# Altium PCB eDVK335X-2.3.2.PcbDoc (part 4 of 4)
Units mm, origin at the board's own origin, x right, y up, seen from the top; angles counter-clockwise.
Board outline 100.04 x 80.07 mm, 4 copper layers (Top Layer, Layer 1, Layer 2, Bottom Layer), stack 0.569 mm thick; 245 components, 272 nets, 1313 pads, 662 vias.
Unrouted connection lines stored in the file: 1.
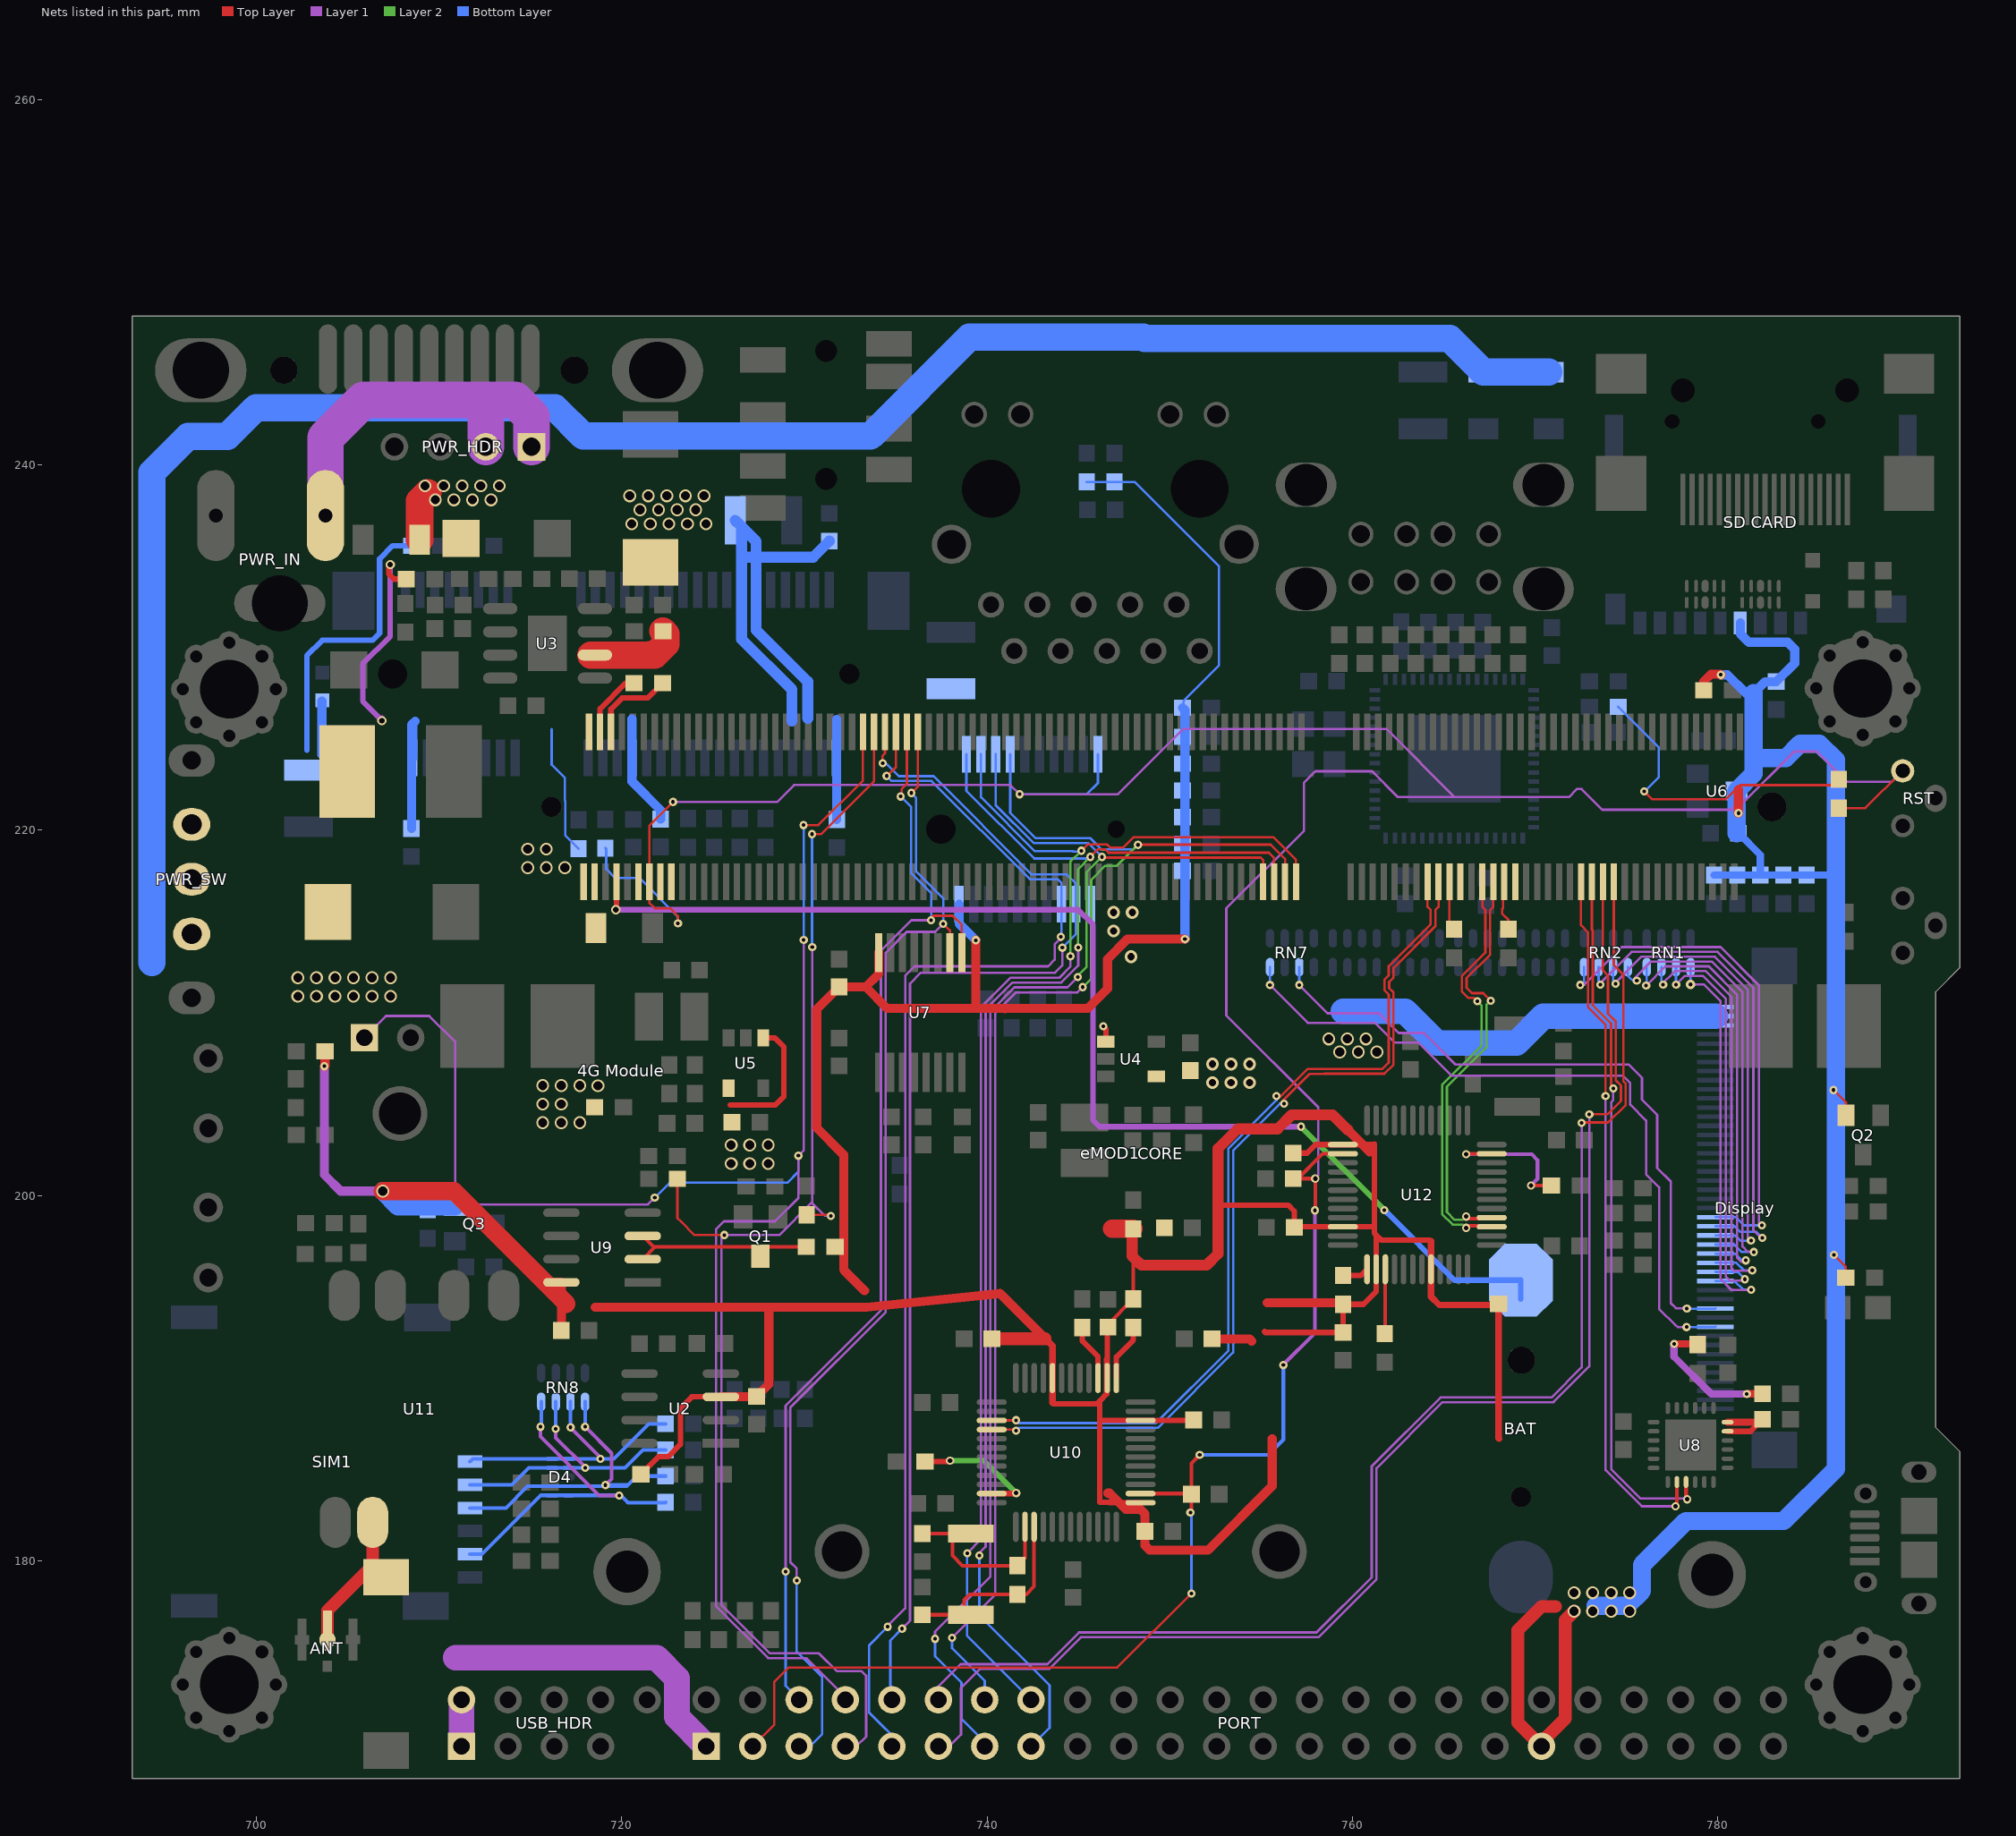
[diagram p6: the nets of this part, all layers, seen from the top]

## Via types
v1: diameter 0.45, hole 0.2, Top Layer to Bottom Layer, tented both sides, 424 vias
v2: diameter 0.7, hole 0.5, Top Layer to Bottom Layer, tented both sides, 146 vias
v3: diameter 0.45, hole 0.25, Top Layer to Bottom Layer, tented both sides, 55 vias
v4: diameter 0.5, hole 0.3, Top Layer to Bottom Layer, tented both sides, 17 vias
v5: diameter 0.7, hole 0.4, Top Layer to Bottom Layer, tented both sides, 13 vias
v6: diameter 0.66, hole 0.33, Top Layer to Bottom Layer, tented both sides, 4 vias
v7: diameter 0.75, hole 0.5, Top Layer to Bottom Layer, tented both sides, 1 vias
v8: diameter 0.5, hole 0.2, Top Layer to Bottom Layer, tented both sides, 1 vias
v9: diameter 0.45, hole 0.3, Top Layer to Bottom Layer, tented both sides, 1 vias

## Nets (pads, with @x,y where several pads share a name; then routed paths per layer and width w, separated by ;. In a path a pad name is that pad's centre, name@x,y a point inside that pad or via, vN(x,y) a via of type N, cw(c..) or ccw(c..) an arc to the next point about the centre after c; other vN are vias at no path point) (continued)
NetR104_2: R104.2 U10.37 | length 3.1
  Top Layer w0.3: U10.37@747.076,190.012 747.076,191.163 748.009,192.096 R104.2@748.009,192.77
NetR107_1: R107.1 U10.11 | length 7.1
  Top Layer w0.3: R107.1@736.604,185.429 737.912,185.429 v3(737.976,185.492) ; U10.11@740.251,183.687 741.568,183.687 v3(741.595,183.714)
  Layer 2 w0.3: v3(737.976,185.492) 739.817,185.492 v3(741.595,183.714)
NetR130_1: R130.1 U12.39 | length 3.5
  Top Layer w0.2: R130.1@761.774,192.446 761.802,192.474 761.802,193.49 U12.39@761.802,195.965
NetR131_2: R131.2 U12.37 | length 1.5
  Top Layer w0.3: R131.2@759.488,195.621 760.457,195.621 U12.37@760.802,195.965
NetR133_1: R133.1 U12.11 | length 8.1
  Top Layer w0.2: v3(766.219,202.263) 766.246,202.29 U12.11@767.627,202.29 ; v3(769.775,200.548) R133.1@770.892,200.548
  Layer 1 w0.2: v3(766.219,202.263) 769.817,202.263 770.13,201.95 770.13,200.904 v3(769.775,200.548)
NetR135_1: R135.1 U10.39 | length 3.1
  Top Layer w0.3: R135.1@745.215,192.77 745.215,192.033 746.076,191.172 U10.39@746.076,190.012
PWRON: CORE.190
R0: Display.22 RN2.8 | length 28.3
  Layer 1 w0.13: v1@772.673,211.53 774.743,213.6 780.16,213.6 782.25,211.51 782.25,198.42 782.3,198.37 v1(782.418,198.37)
  Bottom Layer w0.13: v1@772.676,211.533 RN2.8@772.676,212.509 ; Display.22@779.871,198.819 780.991,198.819 781.44,198.37 v1(782.418,198.37)
  other v1: 772.473,211.53
R1: Display.21 RN2.7 | length 27.8
  Layer 1 w0.13: v1@773.673,211.53 773.673,211.73 775.283,213.34 779.996,213.34 781.95,211.386 781.95,198.1 782.34,197.71 v1@782.34,197.68 ; v1@782.34,197.68 v1(782.438,197.68)
  Bottom Layer w0.13: RN2.7@773.476,212.509 773.476,211.727 v1@773.673,211.53 ; Display.21@779.871,198.319 780.921,198.319 781.22,198.02 782.098,198.02 v1(782.438,197.68)
  other v1: 773.573,211.54
R2: Display.20 RN2.6 | length 25.8
  Layer 1 w0.13: v1@774.473,211.53 774.473,211.73 775.813,213.07 779.841,213.07 781.65,211.261 781.65,197.51 781.71,197.45 781.71,197.421 v1(781.818,197.53)
  Bottom Layer w0.13: RN2.6@774.276,212.509 774.276,211.767 v1@774.493,211.55 ; Display.20@779.871,197.819 780.941,197.819 781.23,197.53 v1(781.818,197.53)
  other v1: 774.413,211.6
R3: Display.19 RN2.5 | length 25.2
  Layer 1 w0.13: v1@775.48,211.64 775.48,211.937 776.353,212.81 779.677,212.81 781.35,211.137 781.35,197.21 781.63,196.93 781.85,196.93 v1@781.92,196.86 ; v1@781.92,196.861 v1(781.968,196.91)
  Bottom Layer w0.13: RN2.5@775.076,212.509 775.076,212.044 v1@775.48,211.64 ; Display.19@779.871,197.319 780.901,197.319 781.31,196.91 v1(781.968,196.91)
  other v1: 775.57,211.77
R4: Display.18 RN1.8 | length 23.9
  Layer 1 w0.13: v1@776.11,211.53 777.13,212.55 779.513,212.55 781.05,211.013 781.05,196.6 781.28,196.37 v1@781.53,196.37 ; v1@781.53,196.3 v1@781.53,196.37 ; v1(781.538,196.45) 781.53,196.441 v1@781.53,196.37
  Bottom Layer w0.13: v1@776.11,211.53 776.113,211.533 RN1.8@776.113,212.509 ; Display.18@779.871,196.819 780.938,196.819 781.307,196.45 v1(781.538,196.45)
  other v1: 776.08,211.49
R5: Display.17 RN1.7 | length 24
  Layer 1 w0.13: v1@776.91,211.54 777.66,212.29 779.349,212.29 780.75,210.889 780.75,196.03 780.9,195.88 781.679,195.88 781.729,195.83 781.81,195.83 v1@781.888,195.908
  Bottom Layer w0.13: v1@776.91,211.54 776.913,211.543 RN1.7@776.913,212.509 ; Display.17@779.871,196.319 781.014,196.319 781.423,195.91 v1(781.888,195.91)
  other v1: 777.01,211.54
R6: Display.16 RN1.6 | length 22.6
  Layer 1 w0.13: v1(777.72,211.55) 778.2,212.03 779.184,212.03 780.45,210.764 780.45,195.544 780.644,195.35 781.41,195.35 781.43,195.37 781.44,195.37 v1@781.488,195.418
  Bottom Layer w0.13: RN1.6@777.713,212.509 777.713,211.557 v1(777.72,211.55) ; Display.16@779.871,195.819 781.089,195.819 v1(781.488,195.42)
R7: Display.15 RN1.5 | length 22.3
  Layer 1 w0.13: v8(778.51,211.56) 779.23,211.56 780.15,210.64 780.15,195.42 780.74,194.83 781.81,194.83 v1(781.83,194.85)
  Bottom Layer w0.13: v8@778.513,211.563 RN1.5@778.513,212.509 ; Display.15@779.871,195.319 780.931,195.319 781.4,194.85 v1(781.83,194.85)
  Bottom Layer w0.2: v8(778.51,211.56) v8@778.513,211.563
RESETOUTn: C70.1 C89.1 CORE.192 eMOD1.2 PORT.3 R8.1 R49.2 RST.1 U10.26 U12.26 | length 198.4
  Top Layer w0.13: v1(722.81,221.55) 721.511,220.251 CORE.192@721.511,217.18 721.511,216.035 721.816,215.729 722.651,215.729 723.08,215.3 v1(723.08,214.9) ; PORT.3@727.17,169.85 728.34,171.02 728.34,173.36 729.14,174.16 747.13,174.16 v1(751.184,178.214) ; R8.1@786.63,221.213 788.083,221.213 RST.1@790.12,223.25
  Top Layer w0.2: U10.26@748.4,183.687 751.147,183.687 C70.1@751.184,183.651 ; v1(751.13,182.65) 751.184,182.704 C70.1@751.184,183.651 ; v1(751.64,185.8) 751.184,185.344 C70.1@751.184,183.651 ; C89.1@756.757,200.929 C89.1@757.011,200.929 ; C89.1@756.884,200.802 C89.1@757.011,200.929 ; v1(757.94,199.19) 757.964,199.214 v3(757.964,200.929) C89.1@757.011,200.929 ; U12.26@759.477,202.29 758.372,202.29 C89.1@757.011,200.929
  Layer 1 w0.13: v1(722.81,221.55) 728.51,221.55 729.44,222.48 741.27,222.48 v1(741.78,221.97) 747.16,221.97 750.73,225.54 761.88,225.54 765.6,221.82 ; v3(757.964,200.929) 758.13,201.096 758.13,204.83 753.1,209.86 753.1,215.73 757.35,219.98 757.35,222.61 757.97,223.23 761.08,223.23 762.49,221.82 765.6,221.82 ; 784.88,224.31 784.19,224.31 ; RST.1@790.12,223.25 789.52,222.65 787.08,222.65 785.42,224.31 784.19,224.31 ; 765.6,221.82 771.85,221.82 772.285,222.255 772.545,222.255 773.68,221.12 780.718,221.12 780.958,221.36 781.24,221.36 784.19,224.31
  Layer 1 w0.2: v1(756.22,190.72) 756.22,190.75 757.94,192.47 v1(757.94,199.19)
  Bottom Layer w0.13: R49.2@719.1,219.023 719.15,218.973 719.15,217.88 719.65,217.38 720.98,217.38 723.08,215.28 v1(723.08,214.9) ; v1(741.78,221.97) 745.46,221.97 746.07,222.58 eMOD1.2@746.07,224.16 ; v1(751.13,182.65) 751.184,182.596 v1(751.184,178.214)
  Bottom Layer w0.2: v1(751.64,185.8) 755.39,185.8 756.22,186.63 v1(756.22,190.72)
SPI1_CS0_/_UART5_TXD: CORE.80 eMOD1.16 PORT.13 | length 75.2
  Top Layer w0.13: v1(746.289,218.54) 746.29,218.538 746.29,218.5 754.98,218.5 755.111,218.369 CORE.80@755.111,217.18
  Layer 1 w0.13: v1(737.15,175.73) 737.15,176.12 740.18,179.15 740.18,210.087 741.493,211.4 744.399,211.4 v1(744.969,211.97)
  Layer 2 w0.13: v1(744.969,211.97) 744.94,211.998 744.94,212 744.97,212.03 744.97,212.04 745.44,212.51 745.44,217.691 v1(746.289,218.54)
  Bottom Layer w0.13: v1(737.15,175.73) 737.15,174.78 737.18,174.75 738.6,173.33 738.6,171.35 739.87,170.08 PORT.13@739.87,169.85 ; eMOD1.16@740.47,224.16 740.47,221.38 742.55,219.3 745.528,219.3 v1(746.289,218.54)
SPI1_D0_/_UART5_CTSN: CORE.78 eMOD1.20 PORT.15 | length 77
  Top Layer w0.13: v1(745.659,218.54) 746.079,218.96 746.462,218.96 746.652,218.77 755.43,218.77 755.711,218.489 CORE.78@755.711,217.18
  Layer 1 w0.13: v1(739.58,180.3) 739.57,180.31 739.57,180.43 739.92,180.78 739.92,210.195 741.385,211.66 744.058,211.66 744.989,212.591 v1(744.989,213.58)
  Layer 2 w0.13: v1(744.989,213.58) 744.97,213.58 744.97,217.851 v1(745.659,218.54)
  Bottom Layer w0.13: eMOD1.20@738.87,224.16 738.87,222.16 742.58,218.45 745.659,218.45 v1(745.659,218.54) ; v1(739.58,180.3) 739.58,177.02 743.42,173.18 743.42,170.86 PORT.15@742.41,169.85
SPI1_D1_/_UART5_RTSN: CORE.74 eMOD1.18 PORT.16 | length 75.1
  Top Layer w0.13: v1(745.169,218.88) 745.509,219.22 746.57,219.22 746.735,219.055 747.457,219.055 748.022,219.62 755.68,219.62 756.911,218.389 CORE.74@756.911,217.18
  Layer 1 w0.13: v1(738.91,180.42) 739.66,181.17 739.66,210.302 741.278,211.92 743.95,211.92 744.56,212.53 v1(744.56,213.1)
  Layer 2 w0.13: v1(744.56,213.1) 744.56,218.271 v1(745.169,218.88)
  Bottom Layer w0.13: v1(738.91,180.42) 738.91,175.89 PORT.16@742.41,172.39 ; eMOD1.18@739.67,224.16 739.67,221.8 742.62,218.85 744.7,218.85 744.71,218.84 745.18,218.84 745.18,218.868 v1(745.169,218.88)
SPI1_SCLK_/_UART5_RXD: CORE.76 eMOD1.14 PORT.14 | length 75.1
  Top Layer w0.13: v1(748.259,219.2) 748.259,219.041 748.26,219.04 748.43,219.21 755.53,219.21 756.311,218.429 CORE.76@756.311,217.18
  Layer 1 w0.13: v1(738.08,175.78) 740.44,178.14 740.44,209.979 741.581,211.12 744.95,211.12 v1(745.24,211.41)
  Layer 2 w0.13: v1(745.24,211.41) 745.7,211.87 745.7,217.28 746.47,218.05 747.109,218.05 v1(748.259,219.2)
  Bottom Layer w0.13: v1(738.08,175.78) 738.08,175.22 739.87,173.43 PORT.14@739.87,172.39 ; eMOD1.14@741.27,224.16 741.27,220.95 742.65,219.57 745.64,219.57 746.25,218.96 748.019,218.96 v1(748.259,219.2)
TXEN: Q1.C R98.2 U9.2 U9.3 | length 10.2
  Top Layer w0.2: U9.2@721.149,196.519 721.822,197.192 ; U9.3@721.149,197.789 721.746,197.192 721.822,197.192 ; R98.2@730.105,197.192 721.822,197.192
UART0_RXD: CORE.28 U8.21 | length 38.7
  Top Layer w0.13: CORE.28@773.111,217.18 773.111,214.566 773.153,214.525 773.153,210.425 774.158,209.42 774.158,205.792 774.211,205.792 v1(774.278,205.86)
  Top Layer w0.2: U8.21@778.262,184.319 778.262,183.438 v3(778.329,183.371)
  Layer 1 w0.13: v1(774.278,205.86) 774.278,205.218 774.17,205.11 774.17,185.028 775.788,183.41 778.29,183.41 v3(778.329,183.371)
UART0_TXD: CORE.30 U8.20 | length 38.8
  Top Layer w0.13: CORE.30@772.511,217.18 772.511,214.799 772.893,214.417 772.893,210.317 773.85,209.36 773.85,205.47 773.84,205.46 773.848,205.46 v1(773.858,205.45)
  Top Layer w0.2: v3(777.694,182.99) 777.762,183.059 U8.20@777.762,184.319
  Layer 1 w0.13: v1(773.858,205.45) 773.858,184.972 775.84,182.99 v3(777.694,182.99)
UART1_RXD: CORE.145 PORT.6 U7.9 | length 62.3
  Top Layer w0.13: v1(735.269,221.85) 735.33,221.85 735.33,222.27 735.611,222.551 CORE.145@735.611,225.38 ; v1(736.94,215.07) 736.94,215.23 737.03,215.32 738.12,215.32 738.615,214.825 U7.9@738.615,213.299
  Layer 1 w0.13: v1(728.97,179.41) 728.97,188.5 734.19,193.72 734.19,213.4 735.86,215.07 v1(736.94,215.07)
  Bottom Layer w0.13: v1(728.97,179.41) 728.97,173.16 729.74,172.39 PORT.6@730.31,172.39 ; v1(735.269,221.85) 735.85,221.268 735.85,217.65 736.94,216.56 v1(736.94,215.07)
UART1_TXD: CORE.143 PORT.5 U7.10 | length 63.5
  Top Layer w0.13: v1(735.85,222.04) 736.211,222.401 CORE.143@736.211,225.38 ; v1(737.6,214.88) 737.965,214.515 U7.10@737.965,213.299
  Layer 1 w0.13: v1(729.58,178.92) 729.58,179.58 729.23,179.93 729.23,188.392 734.45,193.612 734.45,213.292 735.598,214.44 737.16,214.44 v1(737.6,214.88)
  Bottom Layer w0.13: v1(729.58,178.92) 729.58,175.03 730.97,173.64 730.97,170.51 PORT.5@730.31,169.85 ; v1(735.85,222.04) 736.11,221.78 736.11,217.77 737.6,216.28 v1(737.6,214.88)
UART2_RXD: CORE.153 P1.1 PORT.8 | length 98.3
  Top Layer w0.13: v1(729.95,220.28) 730.77,220.28 733.19,222.7 733.19,225.359 CORE.153@733.211,225.38
  Layer 1 w0.13: P1.1@705.91,208.65 707.09,209.83 709.46,209.83 710.89,208.4 710.89,200.27 711.65,199.51 721.43,199.51 v1(721.81,199.89) ; v1(729.96,214) 729.96,214.04 729.97,214.03 729.97,202.48 v1(729.67,202.18) 729.67,199.87 728.39,198.59 725.6,198.59 725.16,198.15 725.16,177.53 728.01,174.68 730.1,174.68 732.39,172.39 PORT.8@732.85,172.39
  Bottom Layer w0.13: v1(721.81,199.89) 722.62,200.7 729.07,200.7 729.67,201.3 729.67,202.01 729.82,202.16 729.69,202.16 v1(729.67,202.18) ; v1(729.96,214) v1@729.96,220.27
  Bottom Layer w0.2: v1(729.95,220.28) v1@729.96,220.27
UART2_TXD: CORE.151 PORT.7 R19.2 R100.1 | length 74.7
  Top Layer w0.13: R19.2@723.047,200.91 723.047,198.773 723.23,198.59 723.98,197.84 v1(725.62,197.84) ; R100.1@730.131,198.945 731.385,198.945 v1(731.44,198.89) ; v1(730.419,219.79) 730.41,219.79 730.45,219.79 730.46,219.78 730.91,219.78 733.811,222.681 CORE.151@733.811,225.38
  Layer 1 w0.13: v1(730.429,213.61) 730.429,199.581 ; v1(731.44,198.89) 731.12,198.89 730.429,199.581 ; PORT.7@732.85,169.85 733.38,170.38 733.38,173.71 733.13,173.96 731.778,173.96 730.798,174.94 728.118,174.94 725.45,177.608 725.45,197.67 v1(725.62,197.84) 728.636,197.84 730.403,199.607 730.429,199.581
  Bottom Layer w0.13: v1(730.419,219.79) 730.419,213.619 730.41,213.61 v1(730.429,213.61)
UART3_RXD: CORE.149 eMOD1.3 PORT.10 | length 68.6
  Top Layer w0.13: v1(734.28,223.67) 734.28,224.08 734.411,224.211 CORE.149@734.411,225.38
  Layer 1 w0.13: v1(735.35,176.29) 735.78,176.72 735.78,211.6 736.38,212.2 741.19,212.2 743.72,212.2 744.12,212.6 v1(744.12,213.57)
  Bottom Layer w0.13: v1(734.28,223.67) 734.46,223.67 735.17,222.96 737.07,222.96 742.45,217.58 744.36,217.58 744.87,217.07 eMOD1.3@744.87,215.96 744.87,214.31 744.13,213.57 v1(744.12,213.57) ; v1(735.35,176.29) 734.7,175.64 734.7,173.08 PORT.10@735.39,172.39
UART3_TXD: CORE.147 eMOD1.5 PORT.9 | length 71.4
  Top Layer w0.13: v1(734.5,222.97) 734.51,222.98 734.53,222.98 735.011,223.461 CORE.147@735.011,225.38
  Layer 1 w0.13: v1(734.56,176.39) 734.56,176.44 735.52,177.4 735.52,212.04 736.03,212.55 743.34,212.55 743.7,212.91 743.7,213.744 743.946,213.99 744.04,213.99 v1(744.04,214.16)
  Bottom Layer w0.13: v1(734.5,222.97) 734.77,222.7 736.963,222.7 742.342,217.32 743.87,217.32 744.07,217.12 eMOD1.5@744.07,215.96 744.07,214.19 v1(744.04,214.16) ; v1(734.56,176.39) 733.54,175.37 733.54,171.7 PORT.9@735.39,169.85
UART4_RXD: CORE.24 PORT.12 | length 75.7
  Top Layer w0.13: v1(772.548,203.98) 772.57,203.98 772.59,204 773.99,204 774.958,204.968 774.958,206.141 774.833,206.267 774.833,212.097 774.311,212.619 CORE.24@774.311,217.18
  Layer 1 w0.13: PORT.12@737.93,172.39 737.33,172.99 737.33,173.11 738.56,174.34 743.29,174.34 745.03,176.08 758.032,176.08 761.056,179.104 761.056,179.865 761.06,179.868 761.06,185.18 764.824,188.944 770.896,188.944 772.548,190.596 v1(772.548,203.98)
UART4_TXD: CORE.26 PORT.11 | length 77
  Top Layer w0.13: v1(772.97,204.45) 773.96,204.45 774.698,205.188 774.698,206.034 774.418,206.314 774.418,209.527 773.993,209.952 773.993,212.037 773.711,212.319 CORE.26@773.711,217.18
  Layer 1 w0.13: PORT.11@737.93,169.85 738.57,170.49 738.57,173.04 739.61,174.08 743.398,174.08 745.138,175.82 758.14,175.82 761.32,179 761.32,185.07 764.934,188.684 771.004,188.684 ; 771.03,188.71 771.004,188.684 ; v1(772.97,204.45) 772.97,190.65 771.004,188.684
USB0_CE: CORE.42
USB0_D_N: CORE.48 U12.3 | length 23.5
  Top Layer w0.13: v1(766.84,210.64) 766.66,210.82 766.34,210.82 765.99,211.17 765.99,212.01 767.281,213.301 767.281,215.632 767.111,215.801 CORE.48@767.111,217.18
  Top Layer w0.2: v3(766.219,198.23) 766.329,198.34 767.576,198.34 U12.3@767.627,198.29
  Layer 2 w0.13: v3@766.329,198.34 766.108,198.34 766.039,198.41 765.492,198.41 764.91,198.992 764.91,206.06 767.075,208.225 767.075,210.405 v1(766.84,210.64)
USB0_D_P: CORE.46 U12.4 | length 23.4
  Top Layer w0.13: v1(767.57,210.67) 767.16,211.08 766.55,211.08 766.25,211.38 766.25,211.902 767.541,213.193 767.541,215.631 767.711,215.801 CORE.46@767.711,217.18
  Top Layer w0.2: v3(766.219,198.85) 766.329,198.74 767.577,198.74 U12.4@767.627,198.79
  Layer 2 w0.13: v3(766.219,198.85) 766.038,198.67 765.6,198.67 765.17,199.1 765.17,205.952 767.335,208.117 767.335,210.435 v1(767.57,210.67)
USB0_ID: CORE.44 R40.1 | length 2.8
  Top Layer w0.13: CORE.44@768.311,217.18 768.245,217.114 768.245,215.735 768.19,215.68 768.19,215.437 768.54,215.087 R40.1@768.54,214.587
USB1_D_N: CORE.58 U10.3 | length 47.7
  Top Layer w0.13: U10.3@740.251,187.687 741.567,187.687 v1(741.58,187.7) ; v1(755.848,205.442) 755.881,205.409 756.041,205.409 757.562,206.93 761.64,206.93 761.99,207.28 761.99,211.01 761.751,211.248 761.751,211.812 761.99,212.05 761.99,212.56 764.281,214.851 764.281,215.632 764.111,215.801 ; 764.11,215.8 764.111,215.801 ; CORE.58@764.111,217.18 764.111,215.801
  Bottom Layer w0.13: v1(741.58,187.7) 741.74,187.54 749.24,187.54 753.21,191.51 753.21,202.578 755.848,205.216 v1(755.848,205.442)
USB1_D_P: CORE.56 U10.4 | length 48.2
  Top Layer w0.13: U10.4@740.251,187.187 741.513,187.187 v1(741.58,187.12) ; v1(756.258,205.032) 756.22,205.07 756.22,205.22 757.665,206.665 758.465,206.665 758.47,206.67 761.748,206.67 762.25,207.172 762.25,211.117 762.011,211.356 762.011,211.704 762.25,211.943 762.25,212.452 764.541,214.743 764.541,215.631 764.711,215.801 CORE.56@764.711,217.18
  Bottom Layer w0.13: v1(741.58,187.12) 741.74,187.28 749.348,187.28 753.47,191.402 753.47,202.47 756.032,205.032 v1(756.258,205.032)
USB1_DRVVBUS: CORE.52
USB1_ID: CORE.54 R153.1 | length 2.6
  Top Layer w0.13: CORE.54@765.311,217.18 765.311,214.896 R153.1@765.57,214.637
USIM_CLK: C16.2 D4.5 D4.6 RN8.2 SIM1.3 | length 15.4
  Layer 1 w0.2: v1(717.2,187.31) 718.77,185.74 718.77,185.59 v1(718.83,185.59)
  Bottom Layer w0.2: SIM1.3@711.695,185.44 711.845,185.59 D4.5@716.19,185.59 D4.6@717.09,185.59 719.56,185.59 721.471,187.501 C16.2@722.398,187.501 ; RN8.2@717.19,188.71 717.19,187.32 v1(717.2,187.31)
USIM_DATA: C15.2 D4.4 D4.7 RN8.3 SIM1.6 | length 15.8
  Layer 1 w0.2: v1(716.39,187.23) 716.39,186.74 718.02,185.11 718.04,185.09 v1(718,185.09)
  Bottom Layer w0.2: SIM1.6@711.695,184.17 713.99,184.17 714.91,185.09 D4.4@716.19,185.09 D4.7@717.09,185.09 v1(718,185.09) 720.17,185.09 721.151,186.071 C15.2@722.398,186.071 ; v1(716.39,187.23) RN8.3@716.39,188.71
USIM_RST: C17.2 D4.2 D4.9 RN8.1 SIM1.2 | length 17.9
  Layer 1 w0.2: v1(717.99,187.34) 719.44,185.89 719.44,184.48 v1(719.11,184.15)
  Bottom Layer w0.2: SIM1.2@711.695,182.9 713.66,182.9 714.85,184.09 D4.2@716.19,184.09 D4.9@717.09,184.09 720.27,184.09 720.21,184.15 ; v1(717.99,187.34) RN8.1@717.99,188.71 ; v1(719.11,184.15) 720.21,184.15 ; C17.2@722.398,184.64 720.82,184.64 720.33,184.15 720.21,184.15
USIM_VCC: C18.2 D4.1 D4.10 RN8.4 SIM1.1 | length 19.8
  Layer 1 w0.2: v1(715.55,187.34) 715.55,186.8 718.77,183.58 v1(719.86,183.58) v1@719.92,183.58
  Bottom Layer w0.2: SIM1.1@711.695,180.36 712.34,180.36 715.57,183.59 D4.1@716.19,183.59 D4.10@717.09,183.59 719.94,183.59 720.34,183.19 722.378,183.19 C18.2@722.398,183.21 ; v1(715.55,187.34) 715.59,187.38 RN8.4@715.59,188.71
VBUS: CORE.199 R5.2 | length 4.7
  Top Layer w0.3: CORE.199@719.411,225.38 719.411,226.631 720.02,227.24 721.417,227.24 R5.2@722.237,228.06
VCLK: Display.10 RN7.4 | length 39.4
  Layer 1 w0.13: v1(755.487,211.53) 757.557,209.46 761.238,209.46 762.318,208.38 763.6,208.38 765.41,206.57 774.79,206.57 775.21,206.15 775.21,204.98 776.08,204.11 776.08,201.16 776.79,200.45 776.79,193.798 777.678,192.91 777.69,192.91 777.8,192.8 v1(778.29,192.8)
  Bottom Layer w0.13: v1@755.49,211.533 RN7.4@755.49,212.509 ; v1(778.29,192.8) 779.853,192.8 Display.10@779.871,192.819
VDD_3V3: "SD CARD.4" C24.1 C35.1 C39.1 C40.1 C59.1 C60.1 C62.2 C73.1 C74.1 C75.1 C90.1 C91.1 C92.1 eMOD1.19 L6.1 L7.1 PORT.37 Q2.2 Q3.2 R4.2 R7.1 R8.2 R9.1 R10.1 R11.1 R12.1 R13.1 R36.2 R38.1 R44.1 R45.2 R65.1 R70.2 R76.1 R87.2 R88.2 R89.2 R90.2 R91.2 R92.2 R98.1 R99.1 R104.1 R131.1 U2.3 U6.3 U7.16 U9.8 U10.25 U10.34 U10.38 U10.44 U12.25 U12.34 U12.38 U12.44 | length 413.6
  Top Layer w0.13: v1(775.97,222.13) 776.4,221.7 780.45,221.7 781.22,222.47 786.313,222.47 R8.2@786.63,222.787 ; v1(786.34,205.78) 787.017,205.103 Q2.2@787.017,204.389 ; v1(786.36,196.75) 787.008,196.102 R70.2@787.008,195.51
  Top Layer w0.2: C73.1@746.575,192.759 746.575,192.911 R104.1@748.009,194.344 748.009,196.621 747.94,196.69
  Top Layer w0.3: R65.1@721.053,184.74 722.013,185.7 722.54,185.7 723.21,186.37 723.21,188.35 723.842,188.982 U2.3@725.427,188.982 ; 743.576,188.656 743.627,188.604 746.007,188.604 746.167,188.764 ; U10.38@746.575,190.012 746.575,191.08 ; C73.1@746.612,192.795 746.575,192.759 746.575,191.08 ; U10.25@748.4,183.187 747.232,183.187 746.695,183.187 746.675,183.206 746.167,183.206 746.167,187.715 ; C74.1@751.311,187.715 751.283,187.687 U10.34@748.4,187.687 746.195,187.687 746.167,187.715 ; 752.64,199.48 756.48,199.48 756.821,199.14 C92.1@756.821,198.262 756.848,198.29 U12.34@759.477,198.29 761.174,198.29 761.202,198.262 ; 755.19,192.55 755.234,192.506 C90.1@759.488,192.506 R131.1@759.488,194.046 760.605,194.046 761.302,194.743 U12.38@761.302,195.965 761.302,197.845 ; C91.1@756.757,202.326 757.519,202.326 757.983,202.79 U12.25@759.477,202.79 760.548,202.79 761.158,202.79 761.202,202.834 761.202,198.262 ; 764.302,197.512 764.25,197.564 761.583,197.564 761.302,197.845 ; 746.167,187.715 746.167,188.764 ; 746.167,188.764 746.545,189.142 746.545,191.05 746.575,191.08 ; 761.202,198.262 761.202,197.945 761.302,197.845
  Top Layer w0.36: 743.183,192.16 743.576,191.767 U10.44@743.576,190.012 743.576,188.656 ; 764.302,197.512 U12.44@764.302,195.965 764.302,194.464 764.758,194.008 767.933,194.008 L6.1@767.997,194.071 767.997,186.724 768.03,186.69
  Top Layer w0.5: v1(703.72,207.08) 703.757,207.117 R99.1@703.757,207.89 R99.1@703.821,207.827 ; U9.8@715.781,195.249 715.801,195.249 U9.8@716.695,195.249 716.695,194.355 716.695,192.619 C59.1@716.686,192.61 ; 718.542,193.884 728.15,193.884 ; U2.3@725.427,188.982 727.36,188.982 C35.1@727.38,189.002 728.05,189.672 728.05,193.784 728.15,193.884 ; 733.3,194.79 732.15,195.94 732.15,202.23 730.67,203.71 730.67,210.196 C62.2@731.895,211.421 733.355,211.421 ; U7.16@734.065,213.299 734.065,212.131 733.355,211.421 ; v1(739.38,213.98) 739.38,210.26 739.37,210.25 ; 740.98,210.23 740.96,210.25 ; 743.183,192.16 740.709,194.634 733.41,193.884 728.15,193.884 ; 746.612,183.714 746.704,183.714 747.232,183.187 747.593,182.825 748.39,182.825 748.644,182.571 C75.1@748.644,181.619 748.644,180.836 748.89,180.59 752.1,180.59 755.61,184.1 755.61,186.67 ; v1(750.83,214.05) 747.7,214.05 746.595,212.945 746.595,211.325 745.52,210.25 740.96,210.25 ; C40.1@752.317,192.153 754.357,192.153 754.48,192.03 ; 755.32,194.13 759.404,194.13 R131.1@759.488,194.046 ; 759.742,203.596 760.548,202.79 760.948,202.39 ; R36.2@779.233,227.66 779.233,228.153 779.62,228.54 780.14,228.54 v1(780.17,228.51) ; v1(781.132,220.94) 781.132,222.218 ; 733.355,211.421 734.526,210.25 739.37,210.25 ; 739.37,210.25 740.96,210.25
  Top Layer w0.6: 747.94,196.69 747.94,198.111 R76.1@748.008,198.179 ; 748.009,196.621 748.44,196.19 752.02,196.19 752.64,196.81 752.64,199.48 752.64,202.57 753.72,203.65 755.9,203.65 756.675,204.425 758.913,204.425 759.742,203.596
  Top Layer w0.7: L7.1@740.262,192.16 743.183,192.16 ; 771.11,177.5 770.35,177.5 769.05,176.2 769.05,171.15 PORT.37@770.35,169.85 770.35,170.07 771.65,171.37 771.65,176.756 v2(772.134,177.24)
  Top Layer w1: v2(706.92,200.24) 710.81,200.24 715.801,195.249 716.695,194.355 716.97,194.08 ; 746.839,198.179 R76.1@748.008,198.179
  Layer 1 w0.5: v1(703.72,207.08) 703.72,201.139 704.619,200.24 v2(706.92,200.24)
  Bottom Layer w0.13: R45.2@745.448,239.071 R44.1@746.972,239.071 748.079,239.071 752.7,234.45 752.7,229.03 750.75,227.08 750.75,226.653 R87.2@750.75,217.53 ; R38.1@774.548,226.755 776.77,224.533 776.77,222.9 775.98,222.11 775.98,222.12 v1(775.97,222.13)
  Bottom Layer w0.4: R7.1@779.79,217.547 R9.1@781.06,217.547 R10.1@782.33,217.547 ; C24.1@781.132,219.84 782.33,218.642 R10.1@782.33,217.547 ; 786.46,217.51 786.423,217.547 R10.1@782.33,217.547
  Bottom Layer w0.5: eMOD1.19@738.47,215.96 738.47,214.89 v1(739.38,213.98) ; R4.2@750.703,226.7 750.75,226.653 750.83,226.573 v1(750.83,214.05) ; v1(780.17,228.51) 780.53,228.51 781.54,227.5 781.97,227.5 782.602,228.132 C60.1@783.2,228.132 784.21,229.142 784.21,229.91 783.83,230.29 781.7,230.29 781.234,230.756 781.234,231.347 ; U6.3@781.03,222.15 U6.3@781.132,222.048
  Bottom Layer w1: v2(706.92,200.24) 707.76,199.4 Q3.2@710.87,199.4 ; v2@773.32,177.54 775.03,177.54 775.85,178.36 775.85,179.78 778.25,182.18 783.6,182.18 786.46,185.04 786.46,217.51 786.46,223.845 785.568,224.738 784.498,224.738 783.72,223.96 781.97,223.96 ; C24.1@781.03,219.84 U6.3@781.03,222.15 781.97,223.09 781.97,223.96 ; 781.97,227.5 781.97,223.96
  other v2: 773.15,177.24 774.166,177.24 775.182,177.24 772.134,178.256 773.15,178.256 774.166,178.256 775.182,178.256
VDD_4G: "4G Module.2" "4G Module.24" "4G Module.39" "4G Module.41" "4G Module.52" C20.2 C21.2 C22.2 C23.2 CC1.2 CC2.2 CC3.2 R47.2 R48.2 R50.2 R79.1 | length 74.8
  Bottom Layer w0.13: 716.16,225.53 716.16,223.59 716.89,222.86 716.89,221.621 716.906,221.605 716.906,219.716 R48.2@717.63,218.993
  Bottom Layer w0.3: 702.77,224.38 702.76,224.39 702.76,229.55 703.61,230.4 706.36,230.4 706.746,230.786 706.746,234.854 706.74,234.86 707.46,235.58 R50.2@708.503,235.58
  Bottom Layer w0.5: 703.59,224.13 R47.2@703.59,227.058 ; C21.2@708.49,220.092 708.49,223.96 708.49,225.76 708.56,225.83 ; 708.56,223.96 708.56,225.83 ; 708.7,225.97 708.56,225.83 ; 720.56,226.09 720.56,223.96 720.56,222.67 722.13,221.1 C23.2@722.13,220.612 ; C20.2@731.77,220.582 731.76,220.592 731.76,223.96 731.76,226.05 731.77,226.06
  Bottom Layer w0.6: CC1.2@726.211,236.97 CC1.2@726.56,236.621 ; 729.31,225.99 729.31,227.71 726.56,230.46 726.56,233.16 726.56,234.95 ; 730.18,226.13 730.18,228.14 727.36,230.96 727.36,233.16 727.36,234.95 ; C22.2@731.36,235.828 730.482,234.95 727.36,234.95 ; 726.56,234.95 CC1.2@726.56,236.621 ; 726.56,234.95 727.36,234.95 ; CC1.2@726.56,236.621 727.36,235.821 727.36,234.95
  other v2: 715.67,203.99 716.686,203.99 717.702,203.99 715.67,205.006 716.686,205.006 715.67,206.022 716.686,206.022 717.702,206.022 718.7,206.01
VDD_5V: C37.1 C38.1 C48.1 C51.1 CORE.201 CORE.202 CORE.203 CORE.204 Display.43 Display.44 Display.45 eMOD1.1 F1.2 F2.2 L1.2 PORT.1 R5.1 R71.1 U4.1 U4.4 U5.1 U5.4 USB_HDR.1 USB_HDR.2 | length 172.8
  Top Layer w0.3: v4(707.33,234.55) 707.24,234.46 707.24,234.04 707.53,233.75 R71.1@708.203,233.75 ; CORE.201@718.811,225.38 718.811,226.65 720.222,228.06 R5.1@720.663,228.06 ; 725.94,204.95 728.4,204.95 728.88,205.43 728.88,208.14 728.391,208.629 U5.1@727.746,208.629 ; v1(746.36,209.27) 746.506,209.124 U4.1@746.506,208.425
  Layer 1 w0.3: v4(706.87,225.99) 706.87,226.14 706.75,226.14 705.82,227.07 705.82,229.11 707.33,230.62 v4(707.33,234.55)
  Layer 1 w1.4: 710.91,174.69 721.9,174.69 723.02,173.57 723.02,171.46 PORT.1@724.63,169.85 ; USB_HDR.1@711.23,169.85 USB_HDR.2@711.23,172.39
  Bottom Layer w1.4: 759.5,210.09 762.89,210.09 764.63,208.35 768.99,208.35 770.459,209.819 Display.44@779.871,209.819
  Bottom Layer w1.5: 694.28,212.75 694.28,239.58 696.26,241.56 698.41,241.56 699.98,243.13 716.35,243.13 717.9,241.58 733.62,241.58 739.03,246.99 748.55,246.99 748.62,246.92 765.327,246.92 F1.2@767.165,245.082 770.738,245.082 F2.2@770.74,245.079
  other v2: 725.99,201.754 727.006,201.754 728.022,201.754 725.99,202.77 727.006,202.77 728.022,202.77 759.31,207.86 760.326,207.86 761.342,207.86 758.71,208.576 759.726,208.576 760.742,208.576 702.27,210.91 703.286,210.91 704.302,210.91 705.318,210.91 706.334,210.91 707.35,210.91 702.27,211.926 703.286,211.926 704.302,211.926 705.318,211.926 706.334,211.926 707.35,211.926 714.856,217.954 715.872,217.954 716.888,217.954 714.856,218.97 715.872,218.97
  other v5: 752.335,206.186 753.351,206.186 754.367,206.186 752.335,207.202 753.351,207.202 754.367,207.202 747.88,213.08 746.93,214.484 746.93,215.5 747.946,215.5
VDD_12V: C41.1 C42.1 D8.2 PWR_SW.4 R73.1 U3.2 | length 7.9
  Top Layer w1.5: C42.1@708.939,235.9 708.939,238.029 709.38,238.47 ; U3.2@718.31,229.575 721.517,229.575 721.537,229.595 721.805,229.595 722.42,230.21 722.42,230.737 R73.1@722.257,230.9
  other v2: 720.544,236.77 721.56,236.77 722.576,236.77 723.592,236.77 724.608,236.77 721,237.54 722.016,237.54 723.032,237.54 724.048,237.54 709.794,238.09 710.81,238.09 711.826,238.09 712.842,238.09 720.44,238.31 721.456,238.31 722.472,238.31 723.488,238.31 724.504,238.31 709.234,238.86 710.25,238.86 711.266,238.86 712.282,238.86 713.298,238.86
VIN: PWR_HDR.1 PWR_HDR.2 PWR_IN.1 PWR_SW.2 PWR_SW.3 | length 21
  Layer 1 w2: PWR_IN.1@703.78,237.23 703.78,241.47 705.86,243.55 712.6,243.55 ; PWR_HDR.2@712.56,240.99 712.56,243.51 712.6,243.55 ; PWR_HDR.1@715.06,240.99 715.06,242.64 714.15,243.55 712.6,243.55
VIO: C67.2 C68.2 R93.1 U8.5 U8.6 | length 11.7
  Top Layer w0.3: U8.5@780.537,187.094 781.797,187.094 782.297,187.594 C67.2@782.456,187.753
  Top Layer w0.4: v1(777.62,191.88) 778.862,191.88 R93.1@778.9,191.842 ; U8.6@780.537,187.594 C67.2@782.297,187.594 ; v1(781.59,189.14) 781.6,189.15 C68.2@782.456,189.15
  Layer 1 w0.4: v1(777.62,191.88) 777.6,191.86 777.6,191.18 779.64,189.14 v1(781.59,189.14)
VRTC: BAT.1 CORE.198 | length 67
  Top Layer w0.3: v4(719.679,215.65) 719.73,215.701 719.73,215.79 719.711,215.809 CORE.198@719.711,217.18
  Layer 1 w0.3: v4(719.679,215.65) 744.98,215.65 745.8,214.83 745.8,204.124 746.154,203.77 v1(757.18,203.77)
  Layer 2 w0.3: v1(757.18,203.77) v1(761.745,199.205)
  Bottom Layer w0.3: 761.905,199.045 v1(761.745,199.205) 765.582,195.368 BAT.1@769.22,195.368 BAT.1@769.22,194.33
VS: Display.12 RN7.2 | length 37.5
  Layer 1 w0.13: v1(757.087,211.53) 758.637,209.98 761.453,209.98 762.533,208.9 763.92,208.9 765.65,207.17 775.13,207.17 775.85,206.45 775.85,205.25 776.68,204.42 776.68,201.516 777.43,200.766 777.43,194.109 777.709,193.83 778.091,193.83 778.141,193.88 778.26,193.88 778.28,193.86 778.28,193.84 778.308,193.812 v1(778.308,193.81)
  Bottom Layer w0.13: v1@757.09,211.533 RN7.2@757.09,212.509 ; v1(778.308,193.81) 779.862,193.81 Display.12@779.871,193.819
WAKEUP: CORE.188
WARMRESETn: CORE.194
WIFIANT: ANT.1@703.89,175.68 ANT.1@703.89,176.189 onANT.P$FEED U11.6 | length 8.5
  Top Layer w0.7: ANT.1@703.89,175.68 ANT.1@703.89,176.189 703.89,177.28 onANT.P$FEED@706.41,179.8 ; U11.6@706.365,182.11 706.365,179.845 onANT.P$FEED@706.41,179.8 ; onANT.P$FEED@707.1,179.11 onANT.P$FEED@706.41,179.8
X_1: C71.1 R109.2 U10.14 X1.2 | length 10
  Top Layer w0.2: C71.1@736.452,181.492 X1.2@738.103,181.492 ; X1.2@739.119,181.492 X1.2@738.103,181.492 ; U10.14@742.076,181.862 742.076,180.156 R109.2@741.659,179.739 738.649,179.739 738.103,180.285 X1.2@738.103,181.492
X_2: C72.1 R109.1 U10.15 X1.1 | length 11.1
  Top Layer w0.2: C72.1@736.452,177.047 X1.1@739.119,177.047 738.738,177.428 738.738,177.872 739.03,178.165 R109.1@741.659,178.165 742.141,178.165 742.575,178.599 U10.15@742.575,181.862
pads on no net: "4G Module.3" "4G Module.5" "4G Module.6" "4G Module.11" "4G Module.13" "4G Module.16" "4G Module.17" "4G Module.19" "4G Module.23" "4G Module.25" "4G Module.28" "4G Module.30" "4G Module.31" "4G Module.32" "4G Module.33" "4G Module.42" "4G Module.44" "4G Module.45" "4G Module.46" "4G Module.47" "4G Module.48" "4G Module.49" "4G Module.50" "4G Module.51" "4G Module." "4G Module.G1" "4G Module.G2" "4G Module.mPCIe_PIL" "LAN. " "SD CARD." ANT.1@703.877,174.233 BAT.0 BOOT.3 COM1. COM1.1 COM1.4 COM1.6 COM1.7 COM1.8 COM1.9 CORE. CORE.82 CORE.84 CORE.86 CORE.88 CORE.90 CORE.92 CORE.94 CORE.96 CORE.98 CORE.100 CORE.102 CORE.104 CORE.106 CORE.108 CORE.110 CORE.112 CORE.114 CORE.116 CORE.118 CORE.120 CORE.122 CORE.124 CORE.126 CORE.128 CORE.130 CORE.132 CORE.134 CORE.136 CORE.138 CORE.140 CORE.142 CORE.144 CORE.146 CORE.148 CORE.150 CORE.152 CORE.154 CORE.156 CORE.158 CORE.159 CORE.160 CORE.161 CORE.162 CORE.164 CORE.166 CORE.168 CORE.170 CORE.172 CORE.174 CORE.176 CORE.178 CORE.180 CORE.182 CORE.184 CORE.186 CORE.SH1 CORE.SH2 Display.42 eMOD1.0 eMOD1.6 eMOD1.8 eMOD1.10 eMOD1.12 eMOD1.eMode_PIL H1.0 H2.0 H3.0 H4.0 HDMI.14 HDMI.24 HDMI.25 HeadSet.4 HeadSet.5 HeadSet.6 HeadSet.7 HeadSet.24 HeadSet.25 onANT.P$GND P2.2 P3.2 PWR_SW.1 PWR_SW.5 RST.3 S1.1 SIM1.5 U1.28 U7.11 U7.12 U7.13 U7.14 U8.1 U8.10 U8.11 U8.12 U8.13 U8.14 U8.15 U8.17 U8.18 U8.19 U8.22 U8.23 U8.24 U10.23 U10.24 U10.27 U10.28 U10.29 U10.30 U10.31 U10.32 U10.33 U10.35 U10.36 U10.40 U10.41 U10.42 U10.43 U10.45 U10.46 U10.47 U10.48 U12.23 U12.24 U12.27 U12.28 U12.29 U12.30 U12.31 U12.32 U12.33 U12.35 U12.36 U12.40 U12.41 U12.42 U12.43 U12.45 U12.46 U12.47 U12.48 USB_HDR.10
copper on no net: | length 0.3
  Layer 1 w0.2: 698.815,175.07 698.926,175.18 ; 699.325,175.179 699.435,175.07

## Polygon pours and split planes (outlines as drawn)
DGND on Layer 2 "Layer 2-DGND" (solid, pour order 16): 693.2,248.158 693.2,168.09 793.242,168.09 793.242,248.158
no net on Layer 2 "Layer 2-AGND" (solid, pour order 4): 776.097,212.915 782.828,212.915 782.828,207.518 776.16,207.518 776.097,207.582
DGND on Bottom Layer "*" (solid, pour order 18): 693.2,248.158 693.2,168.09 793.242,168.09 793.242,248.158
VDD_5V on Bottom Layer "Bottom Layer-VDD_5V" (solid, pour order 14): 693.59,212.81 708.04,212.81 708.12,212.73 708.12,209.94 707.87,209.69 693.6,209.69 693.57,209.72 693.57,212.76
VIN on Layer 1 "Layer 1-VIN" (solid, pour order 12): 694.07,215.96 694.08,215.95 708.54,215.95 708.59,216 708.59,239.3 708.57,239.28 702.53,239.28 702.56,239.25 702.56,221.45 702.51,221.5 694.07,221.5
DGND on Top Layer "Layer 2-DGND" (solid, pour order 20): 693.2,248.158 693.2,168.09 793.242,168.09 793.242,248.158

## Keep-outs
Keep-Out Layer:
  the board outline again, w0.4

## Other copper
Top Layer:
  rectangle net NetC14_1: 713.05,192.07 715.44,193.45
  rectangle net NetC14_1: 713.05,192.07 714.05,194.39
  rectangle net DGND: 707.21,239.78 707.92,242.24
  rectangle net DGND: 709.74,239.75 710.38,242.26
  rectangle net DGND: 706.17,240.71 711.27,241.34
  rectangle net DGND: 700.67,230.75 702.05,234.07
  rectangle net DGND: 697.76,231.81 704.75,232.98
  rectangle net DGND: 697.18,233.58 698.39,240.47
  rectangle net DGND: 695.82,236.4 699.9,237.89
  rectangle net VDD_5V: 752.8,207.45 761.74,210.43
  rectangle net VDD_5V: 752.8,205.77 755.67,210.43
  rectangle net VDD_3V3: 771.71,176.83 776.14,178.66
  rectangle net VDD_3V3: 770.28,176.83 776.14,178.33
  rectangle net VDD_3V3: 770.28,176.93 772.2,187.8
  rectangle net VDD_3V3: 753.84,185.54 772.2,187.8
  rectangle net VDD_3V3: 753.84,185.54 755.68,196.16
  rectangle net VDD_3V3: 748.76,193.53 755.68,196.16
  rectangle net VDD_3V3: 716.4,193.29 732.6,194.75
  rectangle net VDD_3V3: 732.18,193.29 742.65,198.78
  rectangle net VDD_3V3: 732.18,196.21 750.19,198.78
  rectangle net VIO: 782.02,186.93 782.95,189.73
  rectangle net VIO: 780.17,186.93 782.95,187.81
  rectangle net VDD_5V: 748.76,205.77 754.83,207.58
  rectangle net VDD_4G: 715.28,203.51 719.1,206.52
  rectangle net VDD_5V: 725.336,201.33 728.53,203.32
  rectangle net DGND: 708.7,212.65 714.33,217.14
  rectangle net VDD_5V: 717.44,213.49 718.75,226.51
  rectangle net VDD_5V: 704.87,217.36 718.69,219.57
  rectangle net DGND: 710.46,241.89 717.38,243.11
  rectangle net DGND: 716.07,239.18 725.89,243.11
  rectangle net DGND: 716.07,234.71 719.31,243.11
  rectangle net DGND: 714.79,234.71 719.31,239.17
  rectangle net VDD_5V: 701.65,210.19 708.11,226.6
  rectangle net DGND: 705.02,231.26 706.66,242.3
  rectangle net VDD_12V: 717.59,228.79 727.42,230.31
  rectangle net VDD_12V: 719.75,233.35 727.42,236.27
  rectangle net VDD_12V: 725.05,228.74 727.42,236.27
  rectangle net VDD_12V: 719.49,233.35 725.74,238.83
  rectangle net VDD_12V: 708.3,234.83 714.1,239.28
  rectangle net DGND: 714.79,228.56 717.37,239.17
  rectangle net NetR72_2: 712.17,231.69 714.65,234.27
  rectangle net NetC36_2: 708.97,219.92 714.62,229.06
  region net VDD_3V3: 760.123,202.898 760.123,203.469 758.916,203.469 758.916,202.898
  region net VDD_3V3: 764.441,197.119 764.441,198.008 760.631,198.008 760.631,197.119
  region net VDD_3V3: 761.266,197.119 761.266,203.025 760.631,203.025 760.631,197.119
  rectangle net DGND: 743.27,183.98 745.78,188.04
  rectangle net DGND: 744.9,182.86 745.786,185.746
  region net DGND: 747.055,211.73 747.055,209.063 752.5,209.063 752.5,211.73
  region net DGND: 749.214,205 749.214,204.237 754.94,204.237 754.94,205
  region net NetC46_1: 749.151,203.094 749.151,199.22 751.691,199.22 751.691,203.094
  region net NetC46_1: 742.166,202.967 742.166,199.22 743.499,199.22 743.499,202.967
  region net NetC46_1: 742.166,202.141 742.166,199.22 751.691,199.22 751.691,202.141
  region net NetL2_1: 743.69,206.904 743.69,203.411 747.182,203.411 747.182,206.904
  region net DGND: 724.955,206.111 724.002,206.111 724.002,198.491 724.955,198.491
  region net VDD_5V: 726.542,206.556 725.336,206.556 725.336,201.92 726.542,201.92
  region net NetC49_1: 722.796,205.921 719.43,205.921 719.43,203.635 722.796,203.635
  region net NetC49_1: 722.669,212.906 719.43,212.906 719.43,208.207 722.669,208.207
  region net NetC49_1: 721.462,212.906 719.43,212.906 719.43,203.635 721.462,203.635
  region net NetL3_1: 726.225,211.191 723.367,211.191 723.367,208.08 726.225,208.08
  region net AVDD33_2: 769.838,194.135 769.838,197.183 769.203,197.183 769.203,194.135
  region net AVDD33_2: 770.727,196.992 770.727,197.462 764.822,197.462 764.822,196.992
  region net AVDD33_2: 765.711,202.136 765.711,203.025 763.107,203.025 763.107,202.136
  region net AVDD33_2: 765.711,197.119 765.711,203.025 764.822,203.025 764.822,197.119
  rectangle net AVDD33: 738.42,188.794 739.055,192.16
  rectangle net VDD_3V3: 745.977,183.016 747.183,188.985
  rectangle net VDD_3V3: 743.437,188.223 747.183,188.985
  rectangle net AVDD33: 738.166,188.54 743.056,188.985
  rectangle net AVDD33: 741.341,188.286 743.056,188.985
  rectangle net AVDD33: 742.167,182.87 744.707,183.778
  rectangle net AVDD33: 742.06,182.87 743.056,188.731
  rectangle net VIO: 780.297,187.181 780.805,187.626
  rectangle net NetC69_1: 779.281,188.07 779.789,188.578
  pour cut-out: 711.55,168.09 711.55,179.68 706.319,184.911 704.351,184.911 698.36,178.921 698.36,168.09
  pour cut-out: 693.2,201.894 699.22,201.894 702.141,204.815 702.141,206.783 699.791,209.133 693.2,209.133
  pour cut-out: 693.31,193.59 699.33,193.59 702.251,196.511 702.251,198.479 699.901,200.829 693.31,200.829
Layer 1:
  rectangle net VDD_5V: 709.07,168.9 712.19,190.1
  rectangle net VDD_5V: 709.07,187.74 724.91,190.44
  rectangle net VDD_5V: 722.3,188.07 724.91,202.05
  rectangle net VDD_5V: 746.08,205.73 754.85,207.63
  rectangle net VDD_4G: 715.3,203.6 719.33,209.86
  rectangle net VDD_5V: 711.37,200.45 715.17,211.14
  rectangle net VDD_5V: 746.08,205.73 748.52,216.64
  rectangle net VDD_5V: 716.41,216.03 748.52,218.18
  rectangle net VDD_5V: 712.7,200.45 728.55,203.44
  rectangle net VDD_5V: 714.42,210.17 717.54,219.67
  rectangle net VDD_5V: 701.66,210.17 717.54,212.43
  rectangle net VDD_12V: 709.1,234.83 725.69,239.3
  rectangle net VDD_12V: 708.59,212.65 712.13,239.3
  rectangle net VDD_12V: 694.07,212.65 712.13,215.61
  rectangle net VIN: 694.07,215.96 706.19,221.5
  rectangle net VIN: 711.28,239.93 716.45,244.69
  rectangle net VIN: 702.51,242.18 716.45,244.69
  rectangle net VIN: 702.51,234.05 705.25,244.69
  pour cut-out: 711.55,168.09 711.55,179.68 706.319,184.911 704.351,184.911 698.36,178.921 698.36,168.09
Layer 2:
  pour cut-out: 711.55,168.09 711.55,179.68 706.319,184.911 704.351,184.911 698.36,178.921 698.36,168.09
Bottom Layer:
  rectangle net NetC14_1: 712.41,192.1 715.44,193.45
  rectangle net NetC14_1: 712.41,192.28 713.97,199.02
  rectangle net DGND: 709.68,239.72 710.36,242.11
  rectangle net DGND: 706.2,240.71 711.26,241.39
  rectangle net DGND: 707.22,239.62 707.91,242.12
  rectangle net DGND: 697.43,233.99 698.13,240.21
  rectangle net DGND: 696.1,236.75 699.61,237.56
  rectangle net DGND: 700.03,213.39 704.57,221.21
  rectangle net DGND: 698.04,213.39 701.1,223.64
  rectangle net VDD_4G: 710.38,203.09 719.48,206.76
  rectangle net VDD_4G: 710.38,203.09 712.29,217.28
  rectangle net VDD_4G: 704.75,213.81 712.07,217.28
  rectangle net VDD_4G: 704.75,213.81 707.51,224.13
  rectangle net VDD_5V: 758.15,208.09 758.87,210.71
  rectangle net VDD_5V: 758.74,207.33 761.86,210.71
  rectangle net VDD_3V3: 771.69,177.3 775.6,177.97
  rectangle net VDD_3V3: 771.69,176.85 776.11,178.68
  rectangle net VDD_5V: 745.42,212.38 748.54,216.99
  rectangle net HDMI_1V8: 777.88,222.21 779.49,227.91
  rectangle net HDMI_1V8: 768.13,228.015 769.51,229.63
  rectangle net HDMI_1V8: 776.76,226.5 779.49,227.91
  rectangle net VDD_4G: 736.12,225.14 737.86,228.3
  rectangle net VDD_4G: 703.08,223.59 708.5,225.21
  rectangle net VDD_4G: 702.24,223.02 704.21,225.21
  rectangle net VDD_4G: 707.67,225.14 737.86,226.39
  rectangle net HDMI_1V8: 764.8,220.53 769.4,221.17
  rectangle net HDMI_1V8: 768.31,220.53 769.4,226
  pour cut-out: 711.55,168.09 711.55,179.68 706.319,184.911 704.351,184.911 698.36,178.921 698.36,168.09
  text "d335x-23-11082020" at 716.2,245.76 h2

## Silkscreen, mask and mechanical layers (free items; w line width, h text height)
Top Overlay:
  drawing of 37 lines, arcs and shapes, not listed
  text "7.5~24V DC" at 693.71,242 h1.5
  text "RS485/UART" at 703.12,210.19 h1.5
  text "B   A" at 700.14,203.41 h2 r90
  text "H   L" at 699.97,195.12 h2 r90
  text "Rev 2.3" at 700.02,184.66 h2.5 r90
  text "eDVK335x" at 697.09,177.05 h4 r90
Bottom Overlay:
  region: 695.74,200.388 695.74,194.498 698.503,194.498 698.503,200.388
  region: 695.95,208.558 695.95,202.668 698.503,202.668 698.503,208.558
  rectangle: 706.38,239.69 710.99,242.71
  rectangle: 711.38,239.69 715.99,242.71
  lines w0.13: 769.32,219.95 769.54,220.17 769.54,220.18 769.33,220.18 769.32,220.17 769.32,219.95 ; 769.575,219.414 770.075,219.914 770.075,219.414 769.575,219.414
  text "GND" at 710.79,242.87 h1.2
  text "7.5~24V" at 715.79,242.88 h1.2
  text "B    A" at 693.993,203.168 h3 r270
  text "L     H" at 693.87,194.95 h3 r270
Bottom Solder:
  drawing of 191 lines, arcs and shapes, not listed
  text "d335x-23-11082020" at 716.2,245.76 h2
Mechanical 1:
  rectangle: 716.161,204.13 782.961,221.28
